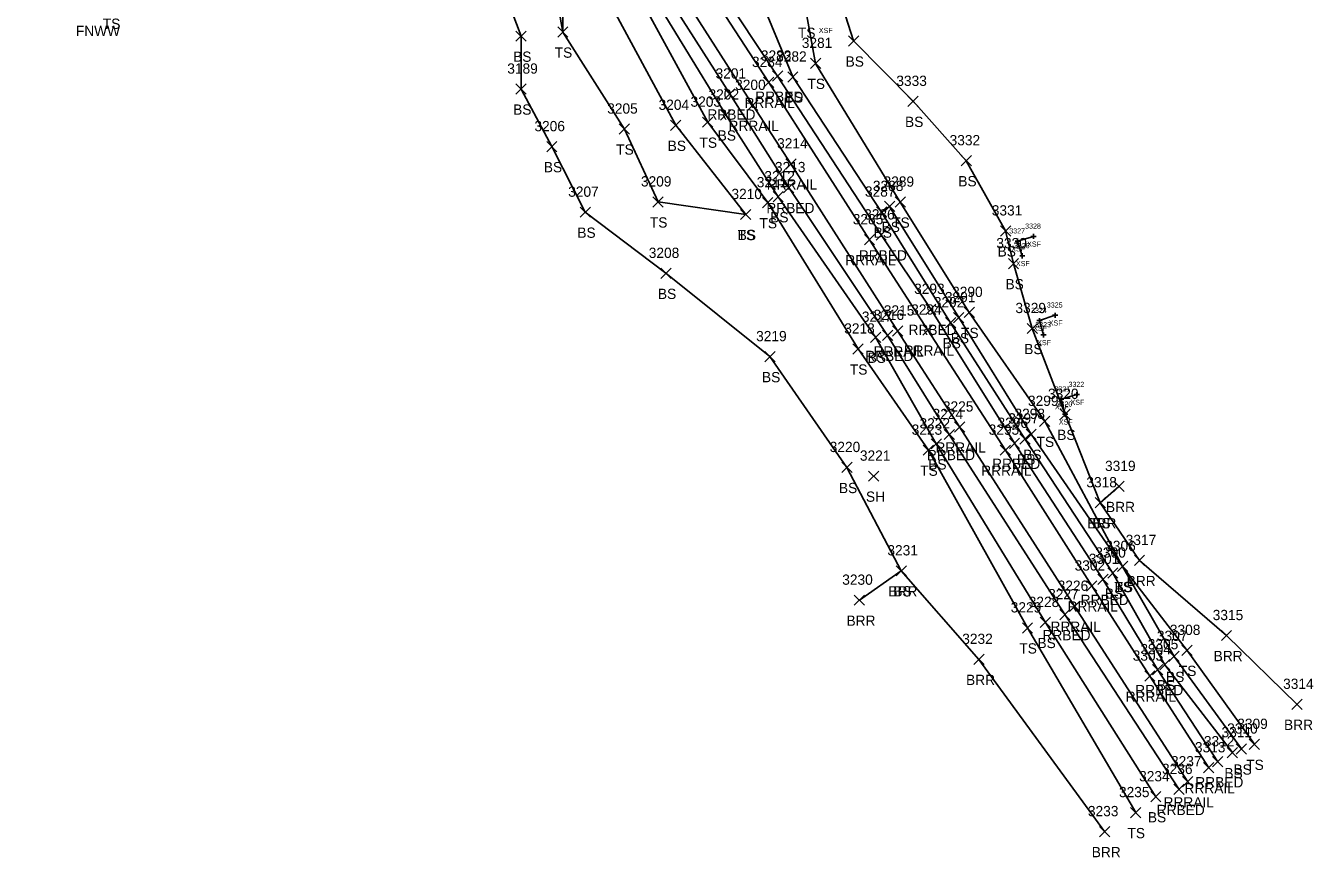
# Model space of a CAD drawing. Extents: x 1505656 to 1508446, y 700805 to 703031.
# Drawn here: x 1506484.4 to 1506735.3, y 701438.5 to 701600.5 of the extents above; entities that cross this region are included whole.
import ezdxf

# ---------------------------------------------------------------- set-up
doc = ezdxf.new("R2010")
doc.units = 0
for name, color, linetype in [('B_A', 7, 'Continuous'), ('B_I', 7, 'Continuous'), ('B_TIC', 7, 'Continuous'), ('BDEFAULT', 7, 'Continuous'), ('L_A', 7, 'Continuous'), ('L_I', 7, 'Continuous'), ('L_TIC', 7, 'Continuous'), ('LABL', 7, 'Continuous'), ('LELB', 7, 'Continuous'), ('R_A', 7, 'Continuous'), ('R_I', 7, 'Continuous'), ('R_TIC', 7, 'Continuous'), ('RR', 7, 'Continuous'), ('RRB', 7, 'Continuous')]:
    doc.layers.add(name, color=color, linetype=linetype)

msp = doc.modelspace()

# ---------------------------------------------------------------- linework, layer by layer
at = {"layer": 'B_TIC'}
for p, q in [((1506677.72, 701558.51), (1506677.8, 701558.51)), ((1506680.81, 701559.44), (1506680.89, 701559.44)), ((1506678.63, 701555.64), (1506678.71, 701555.64)), ((1506681.97, 701543.02), (1506682.05, 701543.02)), ((1506685.04, 701544.07), (1506685.11, 701544.07)), ((1506682.77, 701540.24), (1506682.85, 701540.24)), ((1506686.23, 701527.73), (1506686.31, 701527.73)), ((1506689.26, 701528.61), (1506689.34, 701528.61)), ((1506686.99, 701524.77), (1506687.06, 701524.77))]:
    msp.add_line(p, q, dxfattribs=at)
for points in [[(1506680.81, 701558.94), (1506680.81, 701559.94)], [(1506677.22, 701558.51), (1506678.22, 701558.51)], [(1506677.72, 701558.01), (1506677.72, 701559.01)], [(1506680.31, 701559.44), (1506681.31, 701559.44)], [(1506678.13, 701555.64), (1506679.13, 701555.64)], [(1506678.63, 701555.14), (1506678.63, 701556.14)], [(1506681.47, 701543.02), (1506682.47, 701543.02)], [(1506681.97, 701542.52), (1506681.97, 701543.52)], [(1506684.53, 701544.07), (1506685.53, 701544.07)], [(1506685.03, 701543.57), (1506685.03, 701544.57)], [(1506682.27, 701540.24), (1506683.27, 701540.24)], [(1506682.77, 701539.74), (1506682.77, 701540.74)], [(1506685.73, 701527.73), (1506686.73, 701527.73)], [(1506686.23, 701527.23), (1506686.23, 701528.23)], [(1506688.76, 701528.61), (1506689.76, 701528.61)], [(1506689.26, 701528.11), (1506689.26, 701529.11)], [(1506686.48, 701524.77), (1506687.48, 701524.77)], [(1506686.98, 701524.27), (1506686.98, 701525.27)]]:
    msp.add_lwpolyline(points, dxfattribs=at)
at = {"layer": 'BDEFAULT'}
for points in [[(1506678.63, 701555.64), (1506677.72, 701558.51), (1506680.81, 701559.44)], [(1506682.77, 701540.24), (1506681.97, 701543.02), (1506685.03, 701544.07)], [(1506686.98, 701524.77), (1506686.23, 701527.73), (1506689.26, 701528.61)]]:
    msp.add_lwpolyline(points, dxfattribs=at)
at = {"layer": 'L_TIC'}
for points in [[(1506588.1, 701598.25), (1506590.1, 701600.25)], [(1506590.1, 701598.25), (1506588.1, 701600.25)], [(1506588.1, 701598.25), (1506590.1, 701600.25)], [(1506590.1, 701598.25), (1506588.1, 701600.25)], [(1506579.97, 701597.46), (1506581.97, 701599.46)], [(1506581.97, 701597.46), (1506579.97, 701599.46)], [(1506644.76, 701596.52), (1506646.76, 701598.52)], [(1506646.76, 701596.52), (1506644.76, 701598.52)], [(1506637.35, 701592.16), (1506639.35, 701594.16)], [(1506639.35, 701592.16), (1506637.35, 701594.16)], [(1506632.92, 701589.5), (1506634.92, 701591.5)], [(1506634.92, 701589.5), (1506632.92, 701591.5)], [(1506579.97, 701587.15), (1506581.97, 701589.15)], [(1506581.97, 701587.15), (1506579.97, 701589.15)], [(1506656.34, 701584.76), (1506658.34, 701586.76)], [(1506658.34, 701584.76), (1506656.34, 701586.76)], [(1506616.32, 701580.7), (1506618.32, 701582.7)], [(1506618.32, 701580.7), (1506616.32, 701582.7)], [(1506619.83, 701582.1), (1506621.83, 701584.1)], [(1506621.83, 701582.1), (1506619.83, 701584.1)], [(1506600.08, 701579.36), (1506602.08, 701581.36)], [(1506602.08, 701579.36), (1506600.08, 701581.36)], [(1506610.09, 701580.09), (1506612.09, 701582.09)], [(1506612.09, 701580.09), (1506610.09, 701582.09)], [(1506585.95, 701575.93), (1506587.95, 701577.93)], [(1506587.95, 701575.93), (1506585.95, 701577.93)], [(1506666.72, 701573.19), (1506668.72, 701575.19)], [(1506668.72, 701573.19), (1506666.72, 701575.19)], [(1506606.66, 701565.16), (1506608.66, 701567.16)], [(1506608.66, 701565.16), (1506606.66, 701567.16)], [(1506630.06, 701566.17), (1506632.06, 701568.17)], [(1506632.06, 701566.17), (1506630.06, 701568.17)], [(1506592.48, 701563.16), (1506594.48, 701565.16)], [(1506594.48, 701563.16), (1506592.48, 701565.16)], [(1506623.73, 701562.71), (1506625.73, 701564.71)], [(1506625.73, 701562.71), (1506623.73, 701564.71)], [(1506623.73, 701562.71), (1506625.73, 701564.71)], [(1506625.73, 701562.71), (1506623.73, 701564.71)], [(1506628.01, 701565.01), (1506630.01, 701567.01)], [(1506630.01, 701565.01), (1506628.01, 701567.01)], [(1506650.22, 701563.18), (1506652.22, 701565.18)], [(1506652.22, 701563.18), (1506650.22, 701565.18)], [(1506650.22, 701563.18), (1506652.22, 701565.18)], [(1506652.22, 701563.18), (1506650.22, 701565.18)], [(1506651.77, 701564.28), (1506653.77, 701566.28)], [(1506653.77, 701564.28), (1506651.77, 701566.28)], [(1506653.86, 701565.12), (1506655.86, 701567.12)], [(1506655.86, 701565.12), (1506653.86, 701567.12)], [(1506674.37, 701559.51), (1506676.37, 701561.51)], [(1506676.37, 701559.51), (1506674.37, 701561.51)], [(1506675.91, 701553.13), (1506677.91, 701555.13)], [(1506677.91, 701553.13), (1506675.91, 701555.13)], [(1506608.18, 701551.24), (1506610.18, 701553.24)], [(1506610.18, 701551.24), (1506608.18, 701553.24)], [(1506665.24, 701542.61), (1506667.24, 701544.61)], [(1506667.24, 701542.61), (1506665.24, 701544.61)], [(1506667.29, 701543.63), (1506669.29, 701545.63)], [(1506669.29, 701543.63), (1506667.29, 701545.63)], [(1506663.65, 701541.61), (1506665.65, 701543.61)], [(1506665.65, 701541.61), (1506663.65, 701543.61)], [(1506679.56, 701540.49), (1506681.56, 701542.49)], [(1506681.56, 701540.49), (1506679.56, 701542.49)], [(1506649.05, 701538.79), (1506651.05, 701540.79)], [(1506651.05, 701538.79), (1506649.05, 701540.79)], [(1506645.63, 701536.5), (1506647.63, 701538.5)], [(1506647.63, 701536.5), (1506645.63, 701538.5)], [(1506628.46, 701535.01), (1506630.46, 701537.01)], [(1506630.46, 701535.01), (1506628.46, 701537.01)], [(1506685.98, 701523.77), (1506687.98, 701525.77)], [(1506687.98, 701523.77), (1506685.98, 701525.77)], [(1506682, 701522.4), (1506684, 701524.4)], [(1506684, 701522.4), (1506682, 701524.4)], [(1506660.86, 701518.01), (1506662.86, 701520.01)], [(1506662.86, 701518.01), (1506660.86, 701520.01)], [(1506678.15, 701518.98), (1506680.15, 701520.98)], [(1506680.15, 701518.98), (1506678.15, 701520.98)], [(1506679.36, 701519.87), (1506681.36, 701521.87)], [(1506681.36, 701519.87), (1506679.36, 701521.87)], [(1506659.33, 701516.78), (1506661.33, 701518.78)], [(1506661.33, 701516.78), (1506659.33, 701518.78)], [(1506643.45, 701513.41), (1506645.45, 701515.41)], [(1506645.45, 701513.41), (1506643.45, 701515.41)], [(1506648.67, 701511.72), (1506650.67, 701513.72)], [(1506650.67, 701511.72), (1506648.67, 701513.72)], [(1506696.45, 701509.72), (1506698.45, 701511.72)], [(1506698.45, 701509.72), (1506696.45, 701511.72)], [(1506692.81, 701506.54), (1506694.81, 701508.54)], [(1506694.81, 701506.54), (1506692.81, 701508.54)], [(1506692.81, 701506.54), (1506694.81, 701508.54)], [(1506694.81, 701506.54), (1506692.81, 701508.54)], [(1506700.47, 701495.29), (1506702.47, 701497.29)], [(1506702.47, 701495.29), (1506700.47, 701497.29)], [(1506654.04, 701493.27), (1506656.04, 701495.27)], [(1506656.04, 701493.27), (1506654.04, 701495.27)], [(1506654.04, 701493.27), (1506656.04, 701495.27)], [(1506656.04, 701493.27), (1506654.04, 701495.27)], [(1506695.27, 701492.84), (1506697.27, 701494.84)], [(1506697.27, 701492.84), (1506695.27, 701494.84)], [(1506697.17, 701494.12), (1506699.17, 701496.12)], [(1506699.17, 701494.12), (1506697.17, 701496.12)], [(1506697.17, 701494.12), (1506699.17, 701496.12)], [(1506699.17, 701494.12), (1506697.17, 701496.12)], [(1506645.88, 701487.55), (1506647.88, 701489.55)], [(1506647.88, 701487.55), (1506645.88, 701489.55)], [(1506682.14, 701483.21), (1506684.14, 701485.21)], [(1506684.14, 701483.21), (1506682.14, 701485.21)], [(1506678.64, 701482.15), (1506680.64, 701484.15)], [(1506680.64, 701482.15), (1506678.64, 701484.15)], [(1506717.42, 701480.66), (1506719.42, 701482.66)], [(1506719.42, 701480.66), (1506717.42, 701482.66)], [(1506709.72, 701477.77), (1506711.72, 701479.77)], [(1506711.72, 701477.77), (1506709.72, 701479.77)], [(1506669.18, 701476.02), (1506671.18, 701478.02)], [(1506671.18, 701476.02), (1506669.18, 701478.02)], [(1506705.4, 701474.98), (1506707.4, 701476.98)], [(1506707.4, 701474.98), (1506705.4, 701476.98)], [(1506707.19, 701476.6), (1506709.19, 701478.6)], [(1506709.19, 701476.6), (1506707.19, 701478.6)], [(1506731.14, 701467.26), (1506733.14, 701469.26)], [(1506733.14, 701467.26), (1506731.14, 701469.26)], [(1506718.57, 701457.84), (1506720.57, 701459.84)], [(1506720.57, 701457.84), (1506718.57, 701459.84)], [(1506720.33, 701458.55), (1506722.33, 701460.55)], [(1506722.33, 701458.55), (1506720.33, 701460.55)], [(1506722.86, 701459.46), (1506724.86, 701461.46)], [(1506724.86, 701459.46), (1506722.86, 701461.46)], [(1506703.65, 701449.25), (1506705.65, 701451.25)], [(1506705.65, 701449.25), (1506703.65, 701451.25)], [(1506699.72, 701446.16), (1506701.72, 701448.16)], [(1506701.72, 701446.16), (1506699.72, 701448.16)], [(1506693.67, 701442.45), (1506695.67, 701444.45)], [(1506695.67, 701442.45), (1506693.67, 701444.45)]]:
    msp.add_lwpolyline(points, dxfattribs=at)
at = {"layer": 'LABL'}
for points in [[(1506732.14, 701468.26), (1506718.42, 701481.66), (1506701.47, 701496.29), (1506693.81, 701507.54), (1506697.45, 701510.72)], [(1506646.88, 701488.55), (1506655.04, 701494.27), (1506670.18, 701477.02), (1506694.67, 701443.45)]]:
    msp.add_lwpolyline(points, dxfattribs=at)
at = {"layer": 'LELB'}
for points in [[(1506693.81, 701507.54), (1506686.98, 701524.77), (1506680.56, 701541.49), (1506676.91, 701554.13), (1506675.37, 701560.51), (1506667.72, 701574.19), (1506657.34, 701585.76), (1506645.76, 701597.52), (1506643.12, 701605.75), (1506633.7, 701616.79), (1506631.63, 701625.74), (1506628.74, 701634.64), (1506624.75, 701643.42), (1506617.39, 701650.22), (1506612.39, 701657.74)], [(1506601.12, 701648.07), (1506607.68, 701642.98), (1506616.82, 701635.45), (1506621.47, 701625.76), (1506630.65, 701614.2), (1506636.5, 701603.11), (1506638.35, 701593.16), (1506654.86, 701566.12), (1506668.29, 701544.63), (1506683, 701523.4), (1506698.17, 701495.12), (1506710.72, 701478.77), (1506723.86, 701460.46)], [(1506599.13, 701646.63), (1506607.43, 701632.77), (1506617.78, 701615.55), (1506623.53, 701615.69), (1506633.92, 701590.5), (1506651.22, 701564.18), (1506652.77, 701565.28), (1506666.24, 701543.61), (1506680.36, 701520.87), (1506698.17, 701495.12), (1506708.19, 701477.6), (1506721.33, 701459.55)], [(1506582.97, 701641.95), (1506584.88, 701639.01), (1506582.15, 701637.17), (1506585.92, 701630.58), (1506588.22, 701625.78), (1506590.69, 701624.69), (1506589.01, 701617.06), (1506597.65, 701606.08), (1506611.09, 701581.09), (1506624.73, 701563.71)], [(1506585.06, 701637.58), (1506589.91, 701633.81), (1506603.86, 701610.98), (1506620.83, 701583.1), (1506631.06, 701567.17), (1506650.05, 701539.79), (1506661.86, 701519.01), (1506683.14, 701484.21), (1506704.65, 701450.25)], [(1506588.22, 701625.78), (1506586.26, 701615.35), (1506589.1, 701599.25)], [(1506590.69, 701624.69), (1506601.98, 701609.95), (1506617.32, 701581.7), (1506629.01, 701566.01), (1506646.63, 701537.5), (1506660.33, 701517.78), (1506679.64, 701483.15), (1506700.72, 701447.16)], [(1506589.01, 701617.06), (1506589.1, 701599.25), (1506601.08, 701580.36), (1506607.66, 701566.16), (1506624.73, 701563.71)], [(1506576.21, 701611.04), (1506580.97, 701598.46), (1506580.97, 701588.15), (1506586.95, 701576.93), (1506593.48, 701564.16), (1506609.18, 701552.24), (1506629.46, 701536.01), (1506644.45, 701514.41), (1506655.04, 701494.27)], [(1506651.22, 701564.18), (1506664.65, 701542.61), (1506679.15, 701519.98), (1506696.27, 701493.84), (1506706.4, 701475.98), (1506719.57, 701458.84)]]:
    msp.add_lwpolyline(points, dxfattribs=at)
at = {"layer": 'R_TIC'}
for points in [[(1506628.21, 701588.44), (1506630.21, 701590.44)], [(1506630.21, 701588.44), (1506628.21, 701590.44)], [(1506629.95, 701589.67), (1506631.95, 701591.67)], [(1506631.95, 701589.67), (1506629.95, 701591.67)], [(1506620.62, 701586.19), (1506622.62, 701588.19)], [(1506622.62, 701586.19), (1506620.62, 701588.19)], [(1506625.09, 701583.98), (1506627.09, 701585.98)], [(1506627.09, 701583.98), (1506625.09, 701585.98)], [(1506632.54, 701572.57), (1506634.54, 701574.57)], [(1506634.54, 701572.57), (1506632.54, 701574.57)], [(1506632.12, 701567.95), (1506634.12, 701569.95)], [(1506634.12, 701567.95), (1506632.12, 701569.95)], [(1506647.85, 701557.79), (1506649.85, 701559.79)], [(1506649.85, 701557.79), (1506647.85, 701559.79)], [(1506650.13, 701558.73), (1506652.13, 701560.73)], [(1506652.13, 701558.73), (1506650.13, 701560.73)], [(1506659.81, 701544.23), (1506661.81, 701546.23)], [(1506661.81, 701544.23), (1506659.81, 701546.23)], [(1506659.22, 701540.19), (1506661.22, 701542.19)], [(1506661.22, 701540.19), (1506659.22, 701542.19)], [(1506651.39, 701539.15), (1506653.39, 701541.15)], [(1506653.39, 701539.15), (1506651.39, 701541.15)], [(1506653.34, 701540.01), (1506655.34, 701542.01)], [(1506655.34, 701540.01), (1506653.34, 701542.01)], [(1506665.41, 701521.3), (1506667.41, 701523.3)], [(1506667.41, 701521.3), (1506665.41, 701523.3)], [(1506663.4, 701519.83), (1506665.4, 701521.83)], [(1506665.4, 701519.83), (1506663.4, 701521.83)], [(1506676.11, 701518.12), (1506678.11, 701520.12)], [(1506678.11, 701518.12), (1506676.11, 701520.12)], [(1506674.33, 701516.78), (1506676.33, 701518.78)], [(1506676.33, 701516.78), (1506674.33, 701518.78)], [(1506691.15, 701490.32), (1506693.15, 701492.32)], [(1506693.15, 701490.32), (1506691.15, 701492.32)], [(1506693.35, 701491.61), (1506695.35, 701493.61)], [(1506695.35, 701491.61), (1506693.35, 701493.61)], [(1506687.83, 701486.37), (1506689.83, 701488.37)], [(1506689.83, 701486.37), (1506687.83, 701488.37)], [(1506685.92, 701484.73), (1506687.92, 701486.73)], [(1506687.92, 701484.73), (1506685.92, 701486.73)], [(1506702.48, 701472.75), (1506704.48, 701474.75)], [(1506704.48, 701472.75), (1506702.48, 701474.75)], [(1506703.98, 701474.02), (1506705.98, 701476.02)], [(1506705.98, 701474.02), (1506703.98, 701476.02)], [(1506713.95, 701454.89), (1506715.95, 701456.89)], [(1506715.95, 701454.89), (1506713.95, 701456.89)], [(1506715.7, 701456.07), (1506717.7, 701458.07)], [(1506717.7, 701456.07), (1506715.7, 701458.07)], [(1506708.17, 701450.67), (1506710.17, 701452.67)], [(1506710.17, 701450.67), (1506708.17, 701452.67)], [(1506709.86, 701452.16), (1506711.86, 701454.16)], [(1506711.86, 701452.16), (1506709.86, 701454.16)]]:
    msp.add_lwpolyline(points, dxfattribs=at)
at = {"layer": 'RR'}
for points in [[(1506395.94, 701951.53), (1506421.29, 701912.09), (1506443.95, 701877.07), (1506458.06, 701855.13), (1506477.03, 701825.7), (1506489.95, 701805.7), (1506505.5, 701781.61), (1506516.89, 701763.97), (1506530.74, 701742.3), (1506549.17, 701713.64), (1506561.51, 701694.68), (1506570.71, 701680.31), (1506583.66, 701660.24), (1506594.67, 701642.93), (1506603.16, 701630.09), (1506614.28, 701612.4), (1506629.21, 701589.44), (1506648.85, 701558.79), (1506660.22, 701541.19), (1506675.33, 701517.78), (1506692.15, 701491.32), (1506703.48, 701473.75), (1506714.95, 701455.89)], [(1506391.76, 701949.05), (1506416.43, 701910.5), (1506441.34, 701871.89), (1506453.84, 701852.66), (1506472.45, 701823.58), (1506485.52, 701803.3), (1506501.67, 701778.37), (1506512.79, 701761.07), (1506526.77, 701739.7), (1506545.52, 701710.15), (1506557.59, 701691.64), (1506579.63, 701657.28), (1506590.1, 701641.04), (1506608.44, 701612.67), (1506626.09, 701584.98), (1506633.54, 701573.57), (1506654.34, 701541.01), (1506666.41, 701522.3), (1506688.83, 701487.37), (1506710.86, 701453.16)]]:
    msp.add_lwpolyline(points, dxfattribs=at)
at = {"layer": 'RRB'}
for points in [[(1506597.44, 701645.61), (1506604.77, 701631.09), (1506615.72, 701613.67), (1506630.95, 701590.67), (1506651.13, 701559.73), (1506660.81, 701545.23), (1506677.11, 701519.12), (1506694.35, 701492.61), (1506704.98, 701475.02), (1506716.7, 701457.07)], [(1506586.72, 701638.87), (1506591.39, 701635.39), (1506605.5, 701612.5), (1506621.62, 701587.19), (1506633.12, 701568.95), (1506652.39, 701540.15), (1506664.4, 701520.83), (1506686.92, 701485.73), (1506709.17, 701451.67)]]:
    msp.add_lwpolyline(points, dxfattribs=at)

# ---------------------------------------------------------------- texts
at = {"layer": 'B_A'}
for p in [(1506638.98, 701599.07), (1506676.48, 701556.51), (1506679.57, 701557.44), (1506677.39, 701553.64), (1506683.79, 701542.07), (1506680.73, 701541.02), (1506681.53, 701538.24), (1506688.02, 701526.61), (1506684.99, 701525.73), (1506685.74, 701522.77)]:
    msp.add_text('XSF', height=1, dxfattribs=at).set_placement(p)
at = {"layer": 'B_I'}
for s, p in [('3327', (1506676.09, 701560.01)), ('3328', (1506679.18, 701560.94)), ('3326', (1506676.97, 701557.14)), ('3324', (1506680.34, 701544.52)), ('3325', (1506683.4, 701545.57)), ('3323', (1506681.14, 701541.74)), ('3321', (1506684.88, 701529.23)), ('3322', (1506687.63, 701530.11)), ('3320', (1506685.31, 701526.27))]:
    msp.add_text(s, height=1, dxfattribs=at).set_placement(p)
at = {"layer": 'L_A'}
for s, p in [('FNWW', (1506494.21, 701598.48)), ('TS', (1506499.45, 701599.88)), ('TS', (1506634.91, 701598.11)), ('BS', (1506579.41, 701593.46)), ('TS', (1506587.51, 701594.25)), ('TS', (1506587.51, 701594.25)), ('BS', (1506644.2, 701592.52)), ('TS', (1506636.76, 701588.16)), ('BS', (1506632.36, 701585.5)), ('BS', (1506579.41, 701583.15)), ('BS', (1506655.78, 701580.76)), ('BS', (1506619.27, 701578.1)), ('TS', (1506599.49, 701575.36)), ('BS', (1506609.53, 701576.09)), ('TS', (1506615.73, 701576.7)), ('BS', (1506585.39, 701571.93)), ('BS', (1506666.16, 701569.19)), ('TS', (1506606.06, 701561.16)), ('TS', (1506627.42, 701561.01)), ('BS', (1506629.5, 701562.17)), ('BS', (1506651.21, 701560.28)), ('TS', (1506653.27, 701561.12)), ('BS', (1506591.92, 701559.16)), ('TS', (1506623.14, 701558.71)), ('BS', (1506623.17, 701558.71)), ('BS', (1506649.66, 701559.18)), ('BS', (1506649.66, 701559.18)), ('BS', (1506673.81, 701555.51)), ('BS', (1506675.35, 701549.13)), ('BS', (1506607.62, 701547.24)), ('BS', (1506663.09, 701537.61)), ('BS', (1506664.68, 701538.61)), ('TS', (1506666.7, 701539.63)), ('BS', (1506679, 701536.49)), ('BS', (1506648.49, 701534.79)), ('BS', (1506627.9, 701531.01)), ('TS', (1506645.03, 701532.5)), ('TS', (1506681.41, 701518.4)), ('BS', (1506685.43, 701519.77)), ('BS', (1506677.59, 701514.98)), ('BS', (1506678.81, 701515.87)), ('TS', (1506658.74, 701512.78)), ('BS', (1506660.3, 701514.01)), ('BS', (1506642.89, 701509.41)), ('SH', (1506648.16, 701507.72)), ('BRR', (1506694.94, 701505.72)), ('BRR', (1506691.3, 701502.54)), ('BS', (1506692.25, 701502.54)), ('TS', (1506696.58, 701490.12)), ('BS', (1506696.62, 701490.12)), ('BRR', (1506698.96, 701491.29)), ('BRR', (1506652.53, 701489.27)), ('BS', (1506653.48, 701489.27)), ('BS', (1506694.72, 701488.84)), ('BRR', (1506644.37, 701483.55)), ('TS', (1506678.05, 701478.15)), ('BS', (1506681.58, 701479.21)), ('BRR', (1506715.91, 701476.66)), ('BS', (1506706.63, 701472.6)), ('TS', (1506709.13, 701473.77)), ('BRR', (1506667.67, 701472.02)), ('BS', (1506704.84, 701470.98)), ('BRR', (1506729.63, 701463.26)), ('TS', (1506722.26, 701455.46)), ('BS', (1506718.01, 701453.84)), ('BS', (1506719.77, 701454.55)), ('BS', (1506703.09, 701445.25)), ('TS', (1506699.12, 701442.16)), ('BRR', (1506692.16, 701438.45))]:
    msp.add_text(s, height=2, dxfattribs=at).set_placement(p)
at = {"layer": 'L_I'}
for s, p in [('3281', (1506635.66, 701596.16)), ('3282', (1506630.66, 701593.5)), ('3189', (1506578.27, 701591.15)), ('3333', (1506654.08, 701588.76)), ('3202', (1506617.49, 701586.1)), ('3205', (1506597.74, 701583.36)), ('3204', (1506607.75, 701584.09)), ('3203', (1506613.98, 701584.7)), ('3206', (1506583.56, 701579.93)), ('3332', (1506664.46, 701577.19)), ('3212', (1506628.37, 701570.17)), ('3209', (1506604.31, 701569.16)), ('3211', (1506626.89, 701569.01)), ('3288', (1506649.51, 701568.28)), ('3289', (1506651.59, 701569.12)), ('3207', (1506590.14, 701567.16)), ('3210', (1506621.95, 701566.71)), ('3210', (1506621.95, 701566.71)), ('3287', (1506647.96, 701567.18)), ('3287', (1506647.96, 701567.18)), ('3331', (1506672.68, 701563.51)), ('3208', (1506605.84, 701555.24)), ('3330', (1506673.57, 701557.13)), ('3290', (1506664.95, 701547.63)), ('3292', (1506661.39, 701545.61)), ('3291', (1506663.55, 701546.61)), ('3217', (1506647.36, 701542.79)), ('3329', (1506677.29, 701544.49)), ('3218', (1506643.93, 701540.5)), ('3219', (1506626.76, 701539.01)), ('3320', (1506683.64, 701527.77)), ('3299', (1506679.73, 701526.4)), ('3297', (1506675.89, 701522.98)), ('3298', (1506677.1, 701523.87)), ('3223', (1506657.07, 701520.78)), ('3222', (1506658.6, 701522.01)), ('3220', (1506641.1, 701517.41)), ('3221', (1506646.98, 701515.72)), ('3319', (1506694.75, 701513.72)), ('3318', (1506691.11, 701510.54)), ('3318', (1506691.11, 701510.54)), ('3306', (1506694.78, 701498.12)), ('3306', (1506694.78, 701498.12)), ('3317', (1506698.78, 701499.29)), ('3231', (1506652.34, 701497.27)), ('3231', (1506652.34, 701497.27)), ('3300', (1506692.85, 701496.84)), ('3230', (1506643.54, 701491.55)), ('3229', (1506676.37, 701486.15)), ('3228', (1506679.88, 701487.21)), ('3315', (1506715.73, 701484.66)), ('3232', (1506666.92, 701480.02)), ('3307', (1506704.85, 701480.6)), ('3308', (1506707.38, 701481.77)), ('3305', (1506703.07, 701478.98)), ('3314', (1506729.45, 701471.26)), ('3310', (1506718.55, 701462.55)), ('3309', (1506720.51, 701463.46)), ('3311', (1506717.45, 701461.84)), ('3234', (1506701.39, 701453.25)), ('3235', (1506697.46, 701450.16)), ('3233', (1506691.41, 701446.45))]:
    msp.add_text(s, height=2, dxfattribs=at).set_placement(p)
at = {"layer": 'R_A'}
for s, p in [('RRBED', (1506626.59, 701585.67)), ('RRRAIL', (1506624.5, 701584.44)), ('RRBED', (1506617.27, 701582.19)), ('RRRAIL', (1506621.39, 701579.98)), ('RRRAIL', (1506628.83, 701568.57)), ('RRBED', (1506628.76, 701563.95)), ('RRRAIL', (1506644.14, 701553.79)), ('RRBED', (1506646.77, 701554.73)), ('RRBED', (1506656.46, 701540.23)), ('RRBED', (1506648.03, 701535.15)), ('RRRAIL', (1506649.63, 701536.01)), ('RRRAIL', (1506655.52, 701536.19)), ('RRBED', (1506660.05, 701515.83)), ('RRRAIL', (1506661.7, 701517.3)), ('RRRAIL', (1506670.63, 701512.78)), ('RRBED', (1506672.75, 701514.12)), ('RRBED', (1506690, 701487.61)), ('RRRAIL', (1506687.45, 701486.32)), ('RRRAIL', (1506684.13, 701482.37)), ('RRBED', (1506682.56, 701480.73)), ('RRBED', (1506700.63, 701470.02)), ('RRRAIL', (1506698.77, 701468.75)), ('RRRAIL', (1506710.24, 701450.89)), ('RRBED', (1506712.34, 701452.07)), ('RRRAIL', (1506706.15, 701448.16)), ('RRBED', (1506704.81, 701446.67))]:
    msp.add_text(s, height=2, dxfattribs=at).set_placement(p)
at = {"layer": 'R_I'}
for s, p in [('3283', (1506627.69, 701593.67)), ('3284', (1506625.95, 701592.44)), ('3201', (1506618.85, 701590.19)), ('3200', (1506622.67, 701587.98)), ('3214', (1506630.85, 701576.57)), ('3213', (1506630.42, 701571.95)), ('3286', (1506647.81, 701562.73)), ('3285', (1506645.59, 701561.79)), ('3293', (1506657.55, 701548.23)), ('3216', (1506649.64, 701543.15)), ('3215', (1506651.64, 701544.01)), ('3294', (1506656.97, 701544.19)), ('3225', (1506663.15, 701525.3)), ('3224', (1506661.14, 701523.83)), ('3295', (1506672.07, 701520.78)), ('3296', (1506673.79, 701522.12)), ('3301', (1506691.58, 701495.61)), ('3302', (1506688.82, 701494.32)), ('3226', (1506685.52, 701490.37)), ('3227', (1506683.66, 701488.73)), ('3304', (1506701.64, 701478.02)), ('3303', (1506700.14, 701476.75)), ('3312', (1506714.01, 701460.07)), ('3313', (1506712.26, 701458.89)), ('3237', (1506707.6, 701456.16)), ('3236', (1506705.85, 701454.67))]:
    msp.add_text(s, height=2, dxfattribs=at).set_placement(p)

doc.saveas('drawing.dxf')
